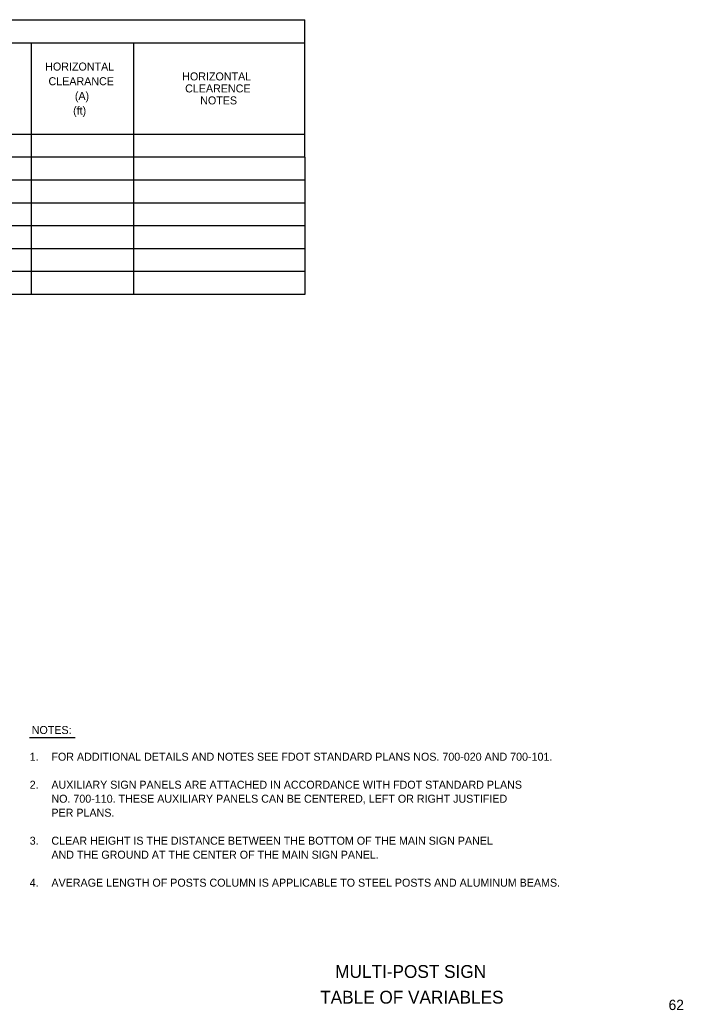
# Model space of a CAD drawing. Extents: x 10268865 to 10269006, y 2142584 to 2142673.
# Drawn here: x 10268948 to 10269006.1, y 2142586.2 to 2142672.9 of the extents above; entities that cross this region are included whole.
import ezdxf

# ---------------------------------------------------------------- set-up
doc = ezdxf.new("R2010")
doc.units = 0
for name, color, linetype in [('TextMisc', 7, 'Continuous'), ('TextNotes', 7, 'Continuous'), ('TextShtNo', 7, 'Continuous'), ('TextTables', 7, 'Continuous')]:
    doc.layers.add(name, color=color, linetype=linetype)

msp = doc.modelspace()

# ---------------------------------------------------------------- linework, layer by layer
at = {"layer": 'TextNotes'}
msp.add_line((10268948.849, 2142610.057), (10268952.852, 2142610.057), dxfattribs=at)
at = {"layer": 'TextTables'}
for p, q in [((10268905.887, 2142672.868), (10268972.968, 2142672.872)), ((10268972.972, 2142648.864), (10268972.968, 2142672.873)), ((10268905.888, 2142670.867), (10268972.969, 2142670.871)), ((10268948.985, 2142670.863), (10268948.988, 2142648.86)), ((10268957.954, 2142670.863), (10268957.957, 2142648.861)), ((10268905.889, 2142662.863), (10268972.97, 2142662.867)), ((10268905.889, 2142660.864), (10268972.97, 2142660.867)), ((10268905.89, 2142658.863), (10268972.971, 2142658.867)), ((10268905.89, 2142656.863), (10268972.971, 2142656.867)), ((10268905.89, 2142654.862), (10268972.971, 2142654.866)), ((10268905.891, 2142652.862), (10268972.972, 2142652.865)), ((10268905.891, 2142650.861), (10268972.972, 2142650.865)), ((10268905.891, 2142648.86), (10268972.972, 2142648.864))]:
    msp.add_line(p, q, dxfattribs=at)

# ---------------------------------------------------------------- texts
at = {"layer": 'TextMisc'}
for s, p in [('    MULTI-POST SIGN     ', (10268973.944, 2142589.019)), ('   TABLE OF VARIABLES   ', (10268973.044, 2142586.769))]:
    msp.add_text(s, height=1.125, rotation=360, dxfattribs=at).set_placement(p)
at = {"layer": 'TextNotes'}
for s, height, p in [('NOTES:', 0.7002, (10268949.049, 2142610.366)), ('1. ', 0.7, (10268948.871, 2142608.028)), ('FOR ADDITIONAL DETAILS AND NOTES SEE FDOT STANDARD PLANS NOS. 700-020 AND 700-101.', 0.7, (10268950.772, 2142608.028)), ('2. ', 0.7, (10268948.871, 2142605.578)), ('AUXILIARY SIGN PANELS ARE ATTACHED IN ACCORDANCE WITH FDOT STANDARD PLANS', 0.7, (10268950.772, 2142605.578)), ('NO. 700-110. THESE AUXILIARY PANELS CAN BE CENTERED, LEFT OR RIGHT JUSTIFIED', 0.7, (10268950.772, 2142604.353)), ('PER PLANS.', 0.7, (10268950.772, 2142603.128)), ('3. ', 0.7, (10268948.871, 2142600.678)), ('CLEAR HEIGHT IS THE DISTANCE BETWEEN THE BOTTOM OF THE MAIN SIGN PANEL', 0.7, (10268950.772, 2142600.678)), ('AND THE GROUND AT THE CENTER OF THE MAIN SIGN PANEL.', 0.7, (10268950.772, 2142599.453)), ('4.', 0.7, (10268948.871, 2142597.003)), ('AVERAGE LENGTH OF POSTS COLUMN IS APPLICABLE TO STEEL POSTS AND ALUMINUM BEAMS.', 0.7, (10268950.772, 2142597.003))]:
    msp.add_text(s, height=height, dxfattribs=at).set_placement(p)
at = {"layer": 'TextShtNo'}
msp.add_text('62', height=0.9, rotation=360, dxfattribs=at).set_placement((10269004.797, 2142586.207))
at = {"layer": 'TextTables'}
for s, p in [('HORIZONTAL', (10268950.23, 2142668.431)), ('HORIZONTAL', (10268962.223, 2142667.568)), ('CLEARANCE', (10268950.519, 2142667.147)), ('CLEARENCE', (10268962.477, 2142666.518)), ('(A)', (10268952.824, 2142665.863)), ('NOTES', (10268963.797, 2142665.468)), ('(ft)', (10268952.67, 2142664.579))]:
    msp.add_text(s, height=0.7003, rotation=0.0098, dxfattribs=at).set_placement(p)

doc.saveas('drawing.dxf')
